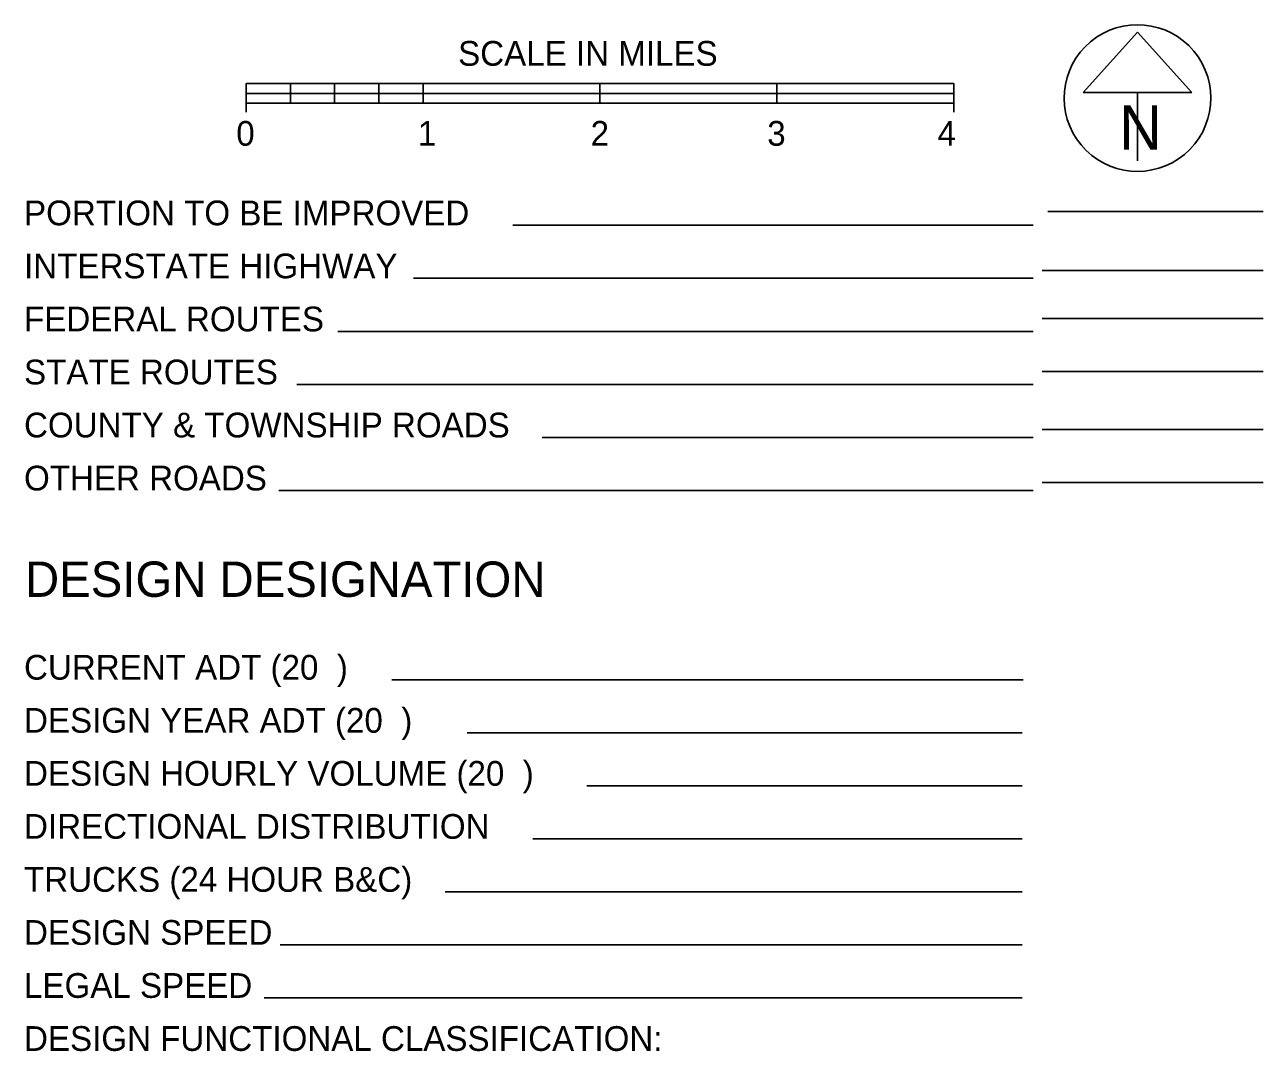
# Model space of a CAD drawing. Extents: x -97 to 34, y -21 to 22.
# Drawn here: x -97.46 to -90.46, y -14.69 to -8.88 of the extents above; entities that cross this region are included whole.
import ezdxf

# ---------------------------------------------------------------- set-up
doc = ezdxf.new("R2010")
doc.units = 0
doc.layers.add('SH_Data', color=7, linetype='Continuous')

msp = doc.modelspace()

# ---------------------------------------------------------------- linework, layer by layer
at = {"layer": 'SH_Data'}
for p, q in [((-91.1671, -8.9227), (-91.4747, -9.264)), ((-90.8595, -9.264), (-91.1671, -8.9227)), ((-96.2063, -9.2136), (-96.2063, -9.3761)), ((-96.2063, -9.2136), (-92.2063, -9.2136)), ((-96.2063, -9.2136), (-96.2063, -9.2698)), ((-95.9563, -9.2136), (-96.2063, -9.2136)), ((-95.9563, -9.3261), (-95.9563, -9.2136)), ((-95.9563, -9.2698), (-95.9563, -9.2136)), ((-95.7063, -9.3261), (-95.7063, -9.2136)), ((-95.7063, -9.2136), (-95.7063, -9.2698)), ((-95.4563, -9.2136), (-95.7063, -9.2136)), ((-95.4563, -9.2136), (-95.4563, -9.3261)), ((-95.4563, -9.2698), (-95.4563, -9.2136)), ((-95.2063, -9.3261), (-95.2063, -9.2136)), ((-95.2063, -9.2136), (-95.2063, -9.2698)), ((-94.2063, -9.2136), (-95.2063, -9.2136)), ((-94.2063, -9.2136), (-94.2063, -9.3261)), ((-94.2063, -9.2698), (-94.2063, -9.2136)), ((-93.2063, -9.3261), (-93.2063, -9.2136)), ((-92.2063, -9.2136), (-93.2063, -9.2136)), ((-93.2063, -9.2136), (-93.2063, -9.2698)), ((-92.2063, -9.3761), (-92.2063, -9.2136)), ((-92.2063, -9.2698), (-92.2063, -9.2136)), ((-96.2063, -9.2698), (-95.9563, -9.2698)), ((-96.2063, -9.2698), (-95.9563, -9.2698)), ((-95.9563, -9.2698), (-95.7063, -9.2698)), ((-95.7063, -9.2698), (-95.9563, -9.2698)), ((-95.9563, -9.2698), (-95.9563, -9.3261)), ((-95.4563, -9.2698), (-95.7063, -9.2698)), ((-95.7063, -9.3261), (-95.7063, -9.2698)), ((-95.7063, -9.2698), (-95.4563, -9.2698)), ((-95.2063, -9.2698), (-95.4563, -9.2698)), ((-95.2063, -9.2698), (-95.4563, -9.2698)), ((-95.4563, -9.2698), (-95.4563, -9.3261)), ((-94.2063, -9.2698), (-95.2063, -9.2698)), ((-95.2063, -9.3261), (-95.2063, -9.2698)), ((-95.2063, -9.2698), (-94.2063, -9.2698)), ((-93.2063, -9.2698), (-94.2063, -9.2698)), ((-93.2063, -9.2698), (-94.2063, -9.2698)), ((-94.2063, -9.2698), (-94.2063, -9.3261)), ((-92.2063, -9.2698), (-93.2063, -9.2698)), ((-93.2063, -9.3261), (-93.2063, -9.2698)), ((-93.2063, -9.2698), (-92.2063, -9.2698)), ((-91.4747, -9.264), (-90.8595, -9.264)), ((-91.1671, -9.264), (-91.1671, -9.6507)), ((-91.1671, -9.2965), (-91.1671, -9.2965)), ((-91.1671, -9.2965), (-91.1671, -9.2965)), ((-96.2063, -9.3261), (-92.2063, -9.3261)), ((-95.9563, -9.3261), (-95.7063, -9.3261)), ((-95.4563, -9.3261), (-95.2063, -9.3261)), ((-94.2063, -9.3261), (-93.2063, -9.3261)), ((-91.6737, -9.9374), (-90.4563, -9.9374)), ((-91.7563, -10.0161), (-94.6977, -10.0161)), ((-90.4563, -10.272), (-91.7063, -10.272)), ((-91.7563, -10.3161), (-95.261, -10.3161)), ((-90.4563, -10.5437), (-91.7063, -10.5437)), ((-91.7563, -10.6161), (-95.6876, -10.6161)), ((-90.4563, -10.8437), (-91.7063, -10.8437)), ((-91.7563, -10.9161), (-95.919, -10.9161)), ((-90.4563, -11.1704), (-91.7063, -11.1704)), ((-91.7563, -11.2161), (-94.5324, -11.2161)), ((-90.4563, -11.4704), (-91.7063, -11.4704)), ((-91.7563, -11.5161), (-96.0215, -11.5161)), ((-91.8139, -12.5865), (-95.3827, -12.5865)), ((-91.8195, -12.8865), (-94.9576, -12.8865)), ((-91.8195, -13.1865), (-94.2805, -13.1865)), ((-91.8195, -13.4865), (-94.5852, -13.4865)), ((-91.8195, -13.7865), (-95.0817, -13.7865)), ((-91.8195, -14.0865), (-96.0146, -14.0865)), ((-91.8195, -14.3865), (-96.1049, -14.3865))]:
    msp.add_line(p, q, dxfattribs=at)
msp.add_arc((-91.1671, -9.2965), 0.4148, 129.77984, 129.76332, dxfattribs=at)

# ---------------------------------------------------------------- texts
for s, height, p in [('SCALE IN MILES', 0.14, (-95.0077, -9.1136)), ('0', 0.14, (-96.262, -9.5661)), ('1', 0.14, (-95.2354, -9.5661)), ('2', 0.14, (-94.2587, -9.5661)), ('3', 0.14, (-93.2603, -9.5661)), ('4', 0.14, (-92.2979, -9.5661)), ('PORTION TO BE IMPROVED', 0.14, (-97.4619, -10.0161)), ('INTERSTATE HIGHWAY', 0.14, (-97.4619, -10.3161)), ('FEDERAL ROUTES', 0.14, (-97.4619, -10.6161)), ('STATE ROUTES', 0.14, (-97.4619, -10.9161)), ('COUNTY & TOWNSHIP ROADS', 0.14, (-97.4619, -11.2161)), ('OTHER ROADS', 0.14, (-97.4619, -11.5161)), ('DESIGN DESIGNATION', 0.2, (-97.4563, -12.1181)), ('CURRENT ADT (20  )', 0.14, (-97.4619, -12.5865)), ('DESIGN YEAR ADT (20  )', 0.14, (-97.4619, -12.8865)), ('DESIGN HOURLY VOLUME (20  )', 0.14, (-97.4619, -13.1865)), ('DIRECTIONAL DISTRIBUTION', 0.14, (-97.4619, -13.4865)), ('TRUCKS (24 HOUR B&C)', 0.14, (-97.4619, -13.7865)), ('DESIGN SPEED', 0.14, (-97.4619, -14.0865)), ('LEGAL SPEED', 0.14, (-97.4619, -14.3865)), ('DESIGN FUNCTIONAL CLASSIFICATION:', 0.14, (-97.4619, -14.6865))]:
    msp.add_text(s, height=height, dxfattribs=at).set_placement(p)
msp.add_text('N', height=0.25, rotation=360, dxfattribs=at).set_placement((-91.2712, -9.5878))

doc.saveas('drawing.dxf')
